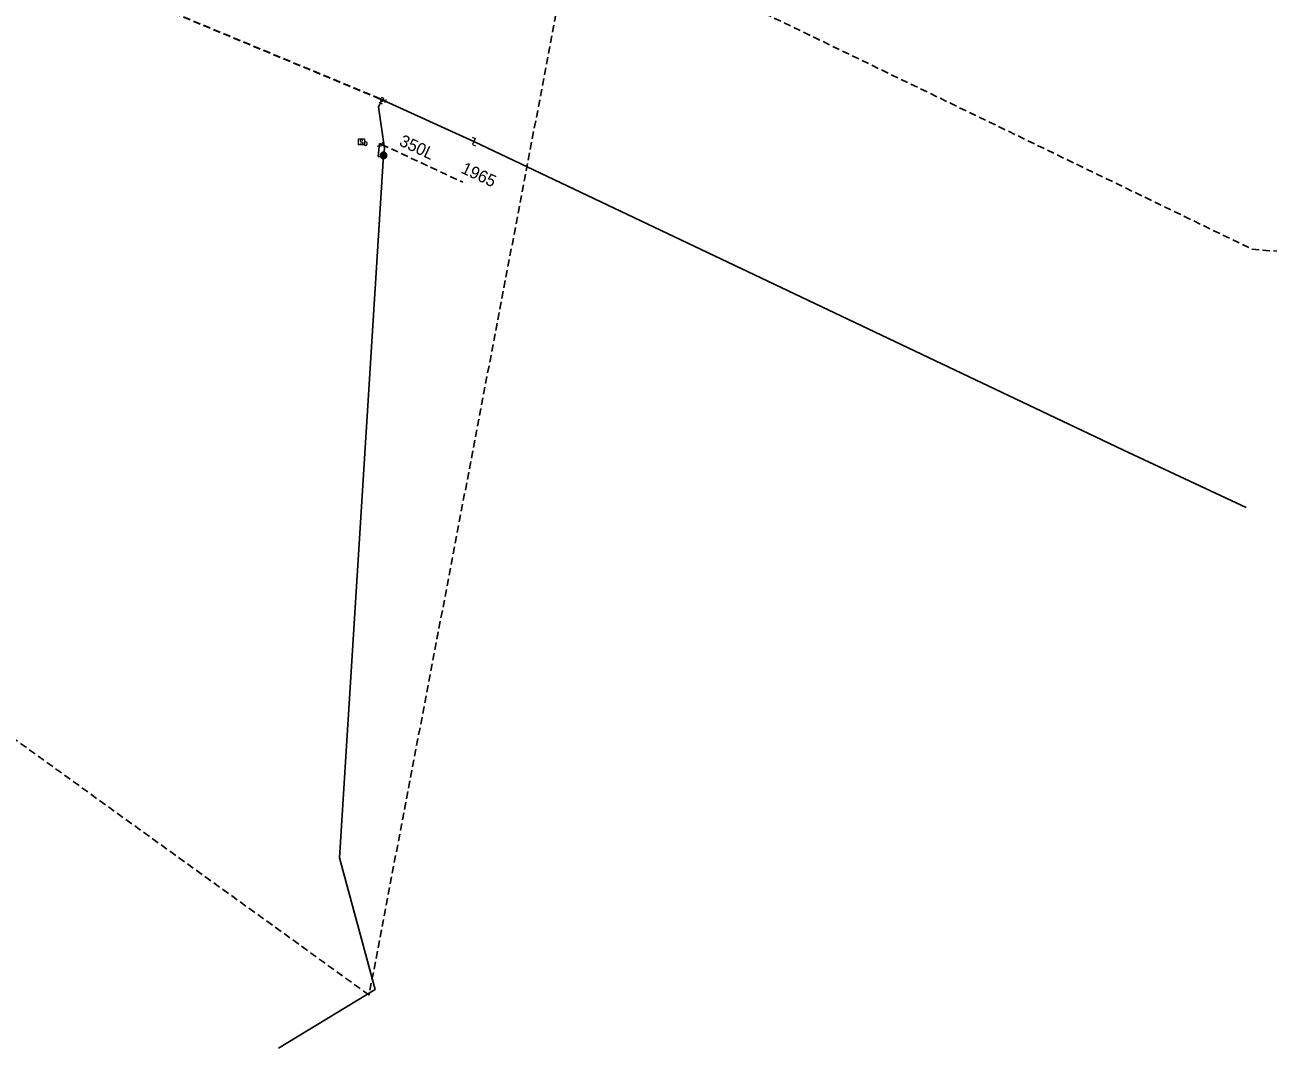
# Model space of a CAD drawing. Extents: x -735085 to -733500, y -1044153 to -1043402.
# Drawn here: x -733894.4 to -733729.1, y -1044152.8 to -1044016.8 of the extents above; entities that cross this region are included whole.
import ezdxf

# ---------------------------------------------------------------- set-up
doc = ezdxf.new("R2010")
doc.units = 0
doc.header["$LTSCALE"] = 0.32
doc.linetypes.add('MEDIUM_DASHED', pattern=[4.5, 3, -1.5])
doc.layers.add('15', color=7, linetype='Continuous')
doc.layers.add('63', color=7, linetype='MEDIUM_DASHED', lineweight=25)
doc.layers.add('8', color=7, linetype='Continuous', lineweight=13)

msp = doc.modelspace()

# ---------------------------------------------------------------- linework, layer by layer
at = {"layer": '63'}
msp.add_lwpolyline([(-734250.468, -1043761.931), (-733815.986, -1043973.969), (-733815.985, -1043973.97), (-733815.983, -1043973.972), (-733815.982, -1043973.973), (-733815.981, -1043973.975), (-733815.981, -1043973.977), (-733815.981, -1043973.978), (-733815.981, -1043973.98), (-733821.622, -1044004.125), (-733821.622, -1044004.125), (-733848.619, -1044145.718), (-733848.619, -1044145.72), (-733848.62, -1044145.722), (-733848.621, -1044145.723), (-733848.623, -1044145.724), (-733848.625, -1044145.725), (-733848.627, -1044145.726), (-733848.629, -1044145.726), (-733848.631, -1044145.726), (-733848.633, -1044145.725), (-733848.634, -1044145.724), (-734009.504, -1044029.598)], dxfattribs=at)
at = {"layer": '8'}
for p, q in [((-733847.331, -1044027.072), (-733846.87, -1044027.306)), ((-733846.341, -1044026.719), (-733846.577, -1044027.179)), ((-733847.02, -1044032.986), (-733847.535, -1044032.934)), ((-733846.858, -1044032.455), (-733847.076, -1044032.924)), ((-733846.861, -1044034.12), (-733846.916, -1044034.635))]:
    msp.add_line(p, q, dxfattribs=at)
at = {"layer": '8', "lineweight": 25}
for p, q in [((-733846.46, -1044026.95), (-733834.69, -1044032.29)), ((-733847.421, -1044034.325), (-733846.89, -1044034.38)), ((-733846.89, -1044034.38), (-733846.62, -1044034.28))]:
    msp.add_line(p, q, dxfattribs=at)
at = {"layer": '8', "linetype": 'MEDIUM_DASHED', "lineweight": 25}
for p, q in [((-733847.239, -1044032.564), (-733846.967, -1044032.691)), ((-733846.967, -1044032.691), (-733836.143, -1044037.73))]:
    msp.add_line(p, q, dxfattribs=at)
at = {"layer": '8', "linetype": 'MEDIUM_DASHED', "lineweight": 35}
msp.add_lwpolyline([(-734156.787, -1043882.494), (-734117.203, -1043901.187), (-734043.806, -1043935.179), (-734015.348, -1043948.221), (-733950.381, -1043983.651), (-733846.87, -1044026.74)], dxfattribs=at)
at = {"layer": '8', "linetype": 'MEDIUM_DASHED', "lineweight": 25}
msp.add_lwpolyline([(-733860.09, -1043932.76), (-733859.77, -1043932.78), (-733841.89, -1043936.04), (-733843.09, -1043963.1), (-733843.68, -1043969.44), (-733845.324, -1043991.459), (-733731.298, -1044046.599), (-733702.378, -1044049.25), (-733692.91, -1044053.837), (-733641.78, -1044080.1), (-733602.168, -1044102.204), (-733602.51, -1044102.94)], dxfattribs=at)
at = {"layer": '8'}
for points in [[(-733846.774, -1044026.529), (-733846.823, -1044026.511), (-733846.875, -1044026.504), (-733846.927, -1044026.509), (-733846.978, -1044026.526), (-733847.022, -1044026.554), (-733847.059, -1044026.591), (-733847.087, -1044026.635), (-733847.105, -1044026.684), (-733847.11, -1044026.737), (-733847.103, -1044026.79), (-733847.085, -1044026.838), (-733847.056, -1044026.882), (-733847.018, -1044026.919), (-733846.973, -1044026.945), (-733846.923, -1044026.962), (-733846.871, -1044026.965), (-733846.819, -1044026.958), (-733846.769, -1044026.938), (-733846.727, -1044026.908), (-733846.691, -1044026.869), (-733846.666, -1044026.823), (-733846.651, -1044026.773), (-733846.649, -1044026.72), (-733846.658, -1044026.668), (-733846.679, -1044026.62), (-733846.71, -1044026.577), (-733846.75, -1044026.544)], [(-733850.022, -1044031.974), (-733849.233, -1044031.974), (-733849.233, -1044032.774), (-733850.022, -1044032.774)], [(-733848.858, -1044032.599), (-733848.864, -1044032.547), (-733848.882, -1044032.497), (-733848.91, -1044032.453), (-733848.948, -1044032.416), (-733848.993, -1044032.389), (-733849.043, -1044032.373), (-733849.095, -1044032.368), (-733849.147, -1044032.375), (-733849.196, -1044032.394), (-733849.24, -1044032.424), (-733849.275, -1044032.463), (-733849.301, -1044032.508), (-733849.316, -1044032.559), (-733849.319, -1044032.611), (-733849.311, -1044032.663), (-733849.29, -1044032.711), (-733849.26, -1044032.754), (-733849.22, -1044032.789), (-733849.174, -1044032.813), (-733849.123, -1044032.827), (-733849.071, -1044032.829), (-733849.019, -1044032.819), (-733848.971, -1044032.797), (-733848.929, -1044032.765), (-733848.896, -1044032.725), (-733848.872, -1044032.678), (-733848.86, -1044032.627)], [(-733846.372, -1044034.167), (-733846.379, -1044034.106), (-733846.397, -1044034.046), (-733846.426, -1044033.991), (-733846.465, -1044033.943), (-733846.512, -1044033.903), (-733846.566, -1044033.873), (-733846.625, -1044033.853), (-733846.686, -1044033.846), (-733846.749, -1044033.85), (-733846.808, -1044033.866), (-733846.864, -1044033.894), (-733846.914, -1044033.931), (-733846.955, -1044033.978), (-733846.987, -1044034.031), (-733847.007, -1044034.09), (-733847.017, -1044034.151), (-733847.014, -1044034.213), (-733846.999, -1044034.273), (-733846.973, -1044034.33), (-733846.936, -1044034.38), (-733846.891, -1044034.423), (-733846.838, -1044034.455), (-733846.781, -1044034.478), (-733846.72, -1044034.488), (-733846.657, -1044034.487), (-733846.597, -1044034.474), (-733846.539, -1044034.449), (-733846.489, -1044034.414), (-733846.445, -1044034.37), (-733846.411, -1044034.318), (-733846.387, -1044034.261), (-733846.375, -1044034.2)], [(-733846.487, -1044034.167), (-733846.492, -1044034.118), (-733846.509, -1044034.071), (-733846.538, -1044034.03), (-733846.576, -1044033.997), (-733846.62, -1044033.973), (-733846.668, -1044033.961), (-733846.718, -1044033.96), (-733846.766, -1044033.972), (-733846.811, -1044033.994), (-733846.848, -1044034.027), (-733846.877, -1044034.067), (-733846.897, -1044034.114), (-733846.904, -1044034.163), (-733846.899, -1044034.213), (-733846.882, -1044034.26), (-733846.855, -1044034.302), (-733846.818, -1044034.336), (-733846.774, -1044034.36), (-733846.727, -1044034.374), (-733846.676, -1044034.375), (-733846.627, -1044034.365), (-733846.583, -1044034.343), (-733846.544, -1044034.311), (-733846.514, -1044034.272), (-733846.495, -1044034.226), (-733846.487, -1044034.176)]]:
    msp.add_lwpolyline(points, close=True, dxfattribs=at)
at = {"layer": '8', "lineweight": 25}
for points in [[(-733846.69, -1044034.17), (-733846.59, -1044033.24), (-733847.359, -1044027.7), (-733847.1, -1044027.19)], [(-733847.1, -1044027.19), (-733846.87, -1044026.74), (-733846.46, -1044026.95)], [(-733847.421, -1044034.325), (-733847.28, -1044032.96), (-733847.239, -1044032.564)], [(-733834.69, -1044032.29), (-733750.289, -1044072.42), (-733748.329, -1044073.33), (-733732.05, -1044080.96)], [(-733846.69, -1044034.17), (-733852.539, -1044127.5), (-733847.82, -1044145.02), (-733860.64, -1044152.79)]]:
    msp.add_lwpolyline(points, dxfattribs=at)
at = {"layer": '8'}
for points in [[(-733849.796, -1044032.557), (-733849.786, -1044032.6), (-733849.764, -1044032.639), (-733849.733, -1044032.67), (-733849.695, -1044032.691), (-733849.652, -1044032.702), (-733849.608, -1044032.7), (-733849.566, -1044032.687), (-733849.529, -1044032.663), (-733849.5, -1044032.63), (-733849.481, -1044032.59), (-733849.473, -1044032.547), (-733849.477, -1044032.503), (-733849.493, -1044032.462), (-733849.519, -1044032.427), (-733849.554, -1044032.4), (-733849.595, -1044032.383), (-733849.62, -1044032.378)], [(-733849.473, -1044032.22), (-733849.478, -1044032.177), (-733849.495, -1044032.136), (-733849.522, -1044032.102), (-733849.559, -1044032.076), (-733849.6, -1044032.061), (-733849.643, -1044032.058), (-733849.686, -1044032.066), (-733849.725, -1044032.086), (-733849.758, -1044032.115), (-733849.781, -1044032.153), (-733849.793, -1044032.195), (-733849.794, -1044032.238), (-733849.782, -1044032.281), (-733849.76, -1044032.318), (-733849.728, -1044032.349), (-733849.69, -1044032.369), (-733849.647, -1044032.378), (-733849.62, -1044032.378)], [(-733834.912, -1044031.731), (-733834.517, -1044031.911), (-733834.875, -1044032.701), (-733834.48, -1044032.88)], [(-733846.259, -1044034.159), (-733846.262, -1044034.114), (-733846.269, -1044034.069), (-733846.281, -1044034.024), (-733846.296, -1044033.982), (-733846.318, -1044033.941), (-733846.343, -1044033.902), (-733846.372, -1044033.867), (-733846.404, -1044033.834), (-733846.44, -1044033.806), (-733846.477, -1044033.781), (-733846.519, -1044033.76), (-733846.561, -1044033.743), (-733846.605, -1044033.731), (-733846.651, -1044033.724), (-733846.696, -1044033.722), (-733846.742, -1044033.724), (-733846.788, -1044033.731), (-733846.831, -1044033.743), (-733846.875, -1044033.76), (-733846.916, -1044033.781), (-733846.953, -1044033.806), (-733846.99, -1044033.834), (-733847.022, -1044033.867), (-733847.051, -1044033.902), (-733847.076, -1044033.941), (-733847.097, -1044033.982), (-733847.112, -1044034.024), (-733847.125, -1044034.069), (-733847.132, -1044034.114), (-733847.134, -1044034.16), (-733847.132, -1044034.205), (-733847.125, -1044034.25), (-733847.112, -1044034.295), (-733847.097, -1044034.337), (-733847.076, -1044034.378), (-733847.051, -1044034.417), (-733847.022, -1044034.452), (-733846.99, -1044034.485), (-733846.953, -1044034.513), (-733846.916, -1044034.538), (-733846.875, -1044034.559), (-733846.831, -1044034.576), (-733846.788, -1044034.587), (-733846.742, -1044034.595), (-733846.696, -1044034.597), (-733846.651, -1044034.595), (-733846.605, -1044034.587), (-733846.561, -1044034.576), (-733846.519, -1044034.559), (-733846.477, -1044034.538), (-733846.44, -1044034.513), (-733846.404, -1044034.485), (-733846.372, -1044034.452), (-733846.343, -1044034.417), (-733846.318, -1044034.378), (-733846.296, -1044034.337), (-733846.281, -1044034.295), (-733846.269, -1044034.25), (-733846.262, -1044034.205), (-733846.259, -1044034.16)]]:
    msp.add_lwpolyline(points, dxfattribs=at)

# ---------------------------------------------------------------- texts
at = {"layer": '15'}
for s, p in [('350L', (-733844.734, -1044032.778)), ('1965', (-733836.514, -1044036.423))]:
    msp.add_text(s, height=1.6, rotation=335, dxfattribs=at).set_placement(p)

doc.saveas('drawing.dxf')
